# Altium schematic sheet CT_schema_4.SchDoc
size 221 x 258 mm
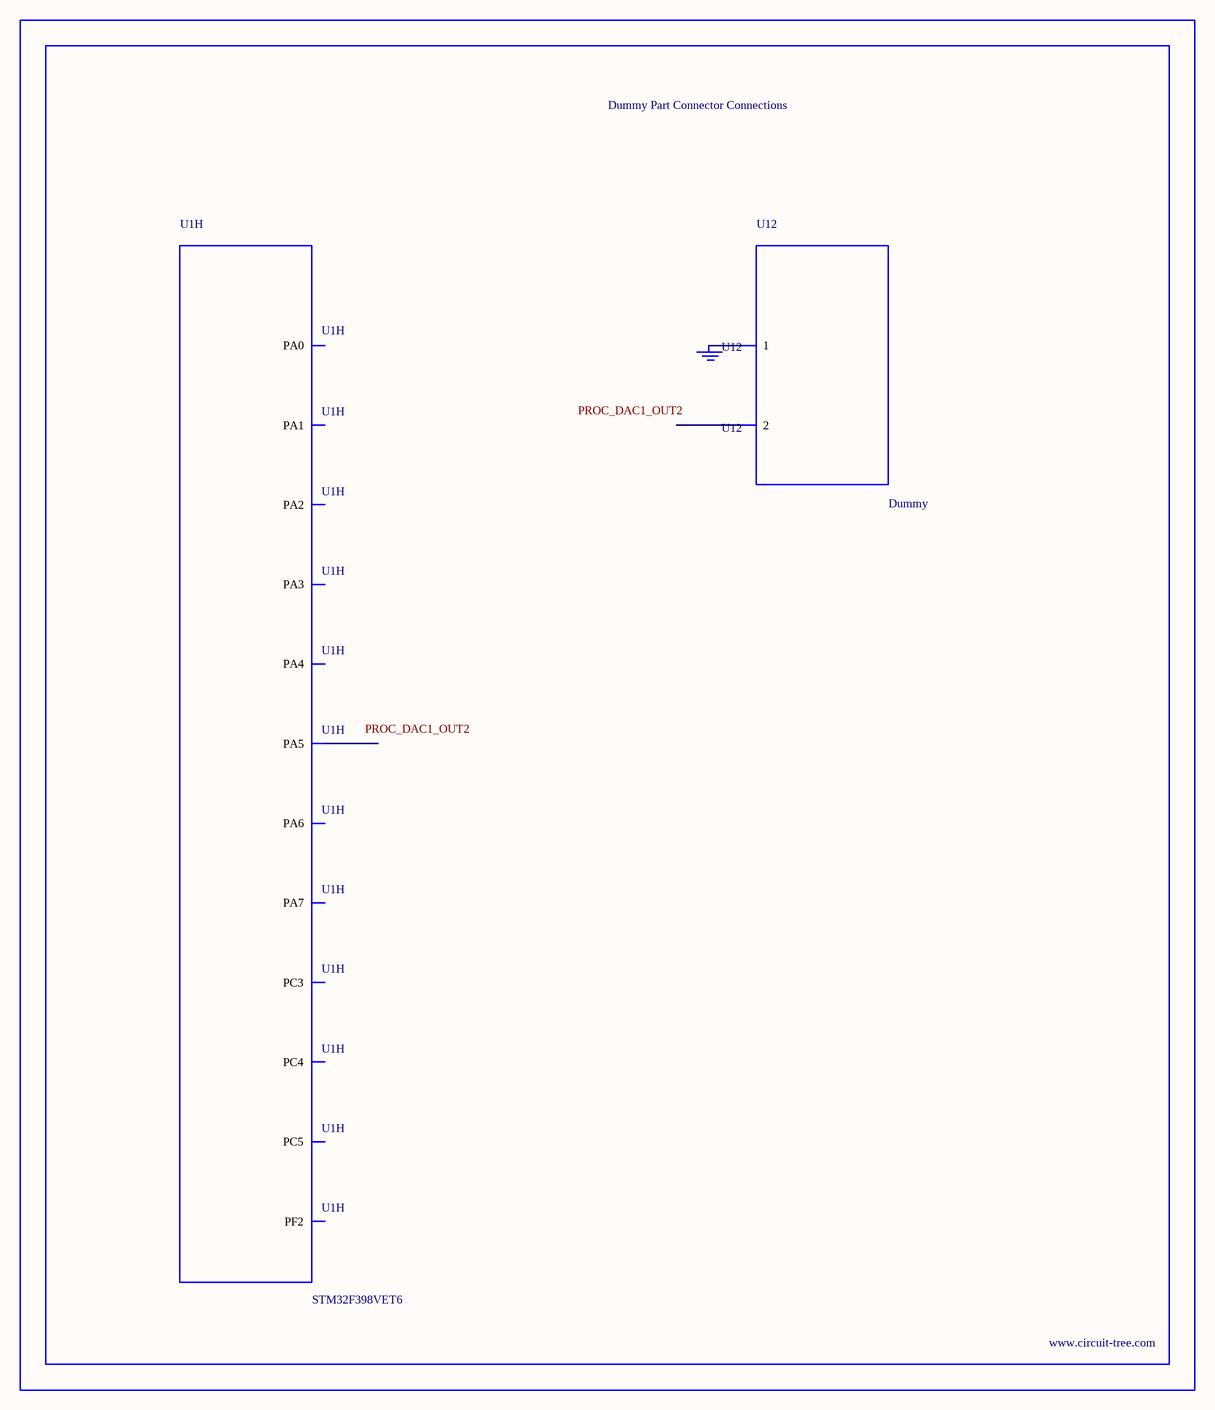
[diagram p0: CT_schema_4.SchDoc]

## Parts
BORDER3  (no value)
GND_INSTANCE_3_0  (no value)
U1  STM32F398VET6  [LQFP100]  (part H of 8)
U12  Dummy  [DUMMY_PACKAGE_144]

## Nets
NetGND_INSTANCE_3_0_0: GND_INSTANCE_3_0.0(GND) U12.1

Not connected (* = marked no-connect by the designer): U1 18(PC3) 19(PF2) 23(PA0) 24(PA1) 25(PA2) 26(PA3) 29(PA4) 30(PA5) 31(PA6) 32(PA7) 33(PC4) 34(PC5); U12 2

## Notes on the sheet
- Labels drawn without touching a wire or pin: PROC_DAC1_OUT2

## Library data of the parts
BORDER3 = BORDER_PAGE3
GND_INSTANCE_3_0 = GND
